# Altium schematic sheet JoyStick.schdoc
size 210 x 148 mm; Symbol: Sheet-Symbol_A2; Company: 嘉立创EDA; Version: V1.0; Page Size: A2; @Project Name: handle-node-1_2026-01-29_18-31-4133; @Page Count: 1; @Update Date: 2026-03-27; @Create Date: 2026-03-27; @Schematic Name: Schematic1; @Page No: 1; @Page Name: P1; Device: Sheet-Symbol_A2; Border: 1; Title Block Position: 3; Width: 826; Height: 582; Region Start: 1; X Region Count: 6; Y Region Count: 4; Blade Width: 10; @Board Name: JoyStick; @Update Time: 15:53:01; @Create Time: 15:53:01
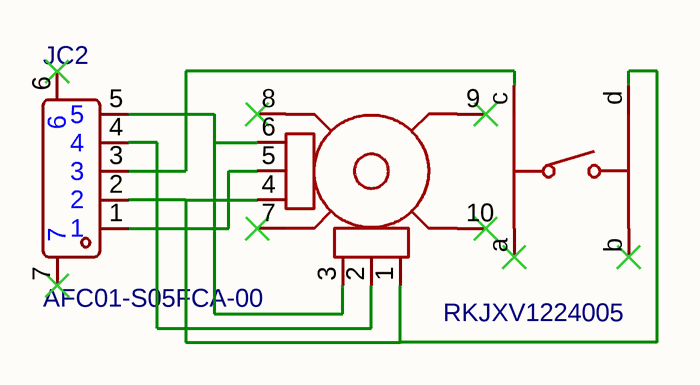
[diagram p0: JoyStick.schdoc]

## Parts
JC2  AFC01-S05FCA-00  [FPC-SMD_AFC01-S05FCA-00]
SW4  RKJXV1224005  [SW-TH_RKJXV1224005]

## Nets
NetJC2_1: JC2.1 JC2.5 SW4.3(A) SW4.5(DTA) SW4.6(B)
NetJC2_2: JC2.2 SW4.1(B) SW4.4(A) SW4.d
NetJC2_3: JC2.3 SW4.c
NetJC2_4: JC2.4 SW4.2(DTA)

Not connected (* = marked no-connect by the designer): JC2 6* 7*; SW4 7(GND)* 8(GND)* 9(GND)* 10(GND)* a* b*

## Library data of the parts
JC2 = AFC01-S05FCA-00: Manufacturer: JS(钜硕电子); Add into BOM: yes; 3D Model: 2ffd2b96456946c691ee1566715954f7; 3D Model Transform: v2:[39.37007874015748,0,0,0,39.37007874015748,0,0,0,39.37007874015748,0,-51.772,0]
SW4 = RKJXV1224005: 操纵杆复位 中央按动开关 适用于航模玩具遥控器电位器、3D摇杆PS4手柄游戏机、无人机摇杆电位器、工业控制器; Manufacturer: ALPSALPINE(阿尔卑斯阿尔派); AddInBom: yes; ModelId: d71267aa208e4a128cc15a7eb8740b010819f05c4eef4c71ace90d822a990e87; ModelTransform: 681.101,838.581,0,0,0,0,-5.905,-5.906,-86.614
